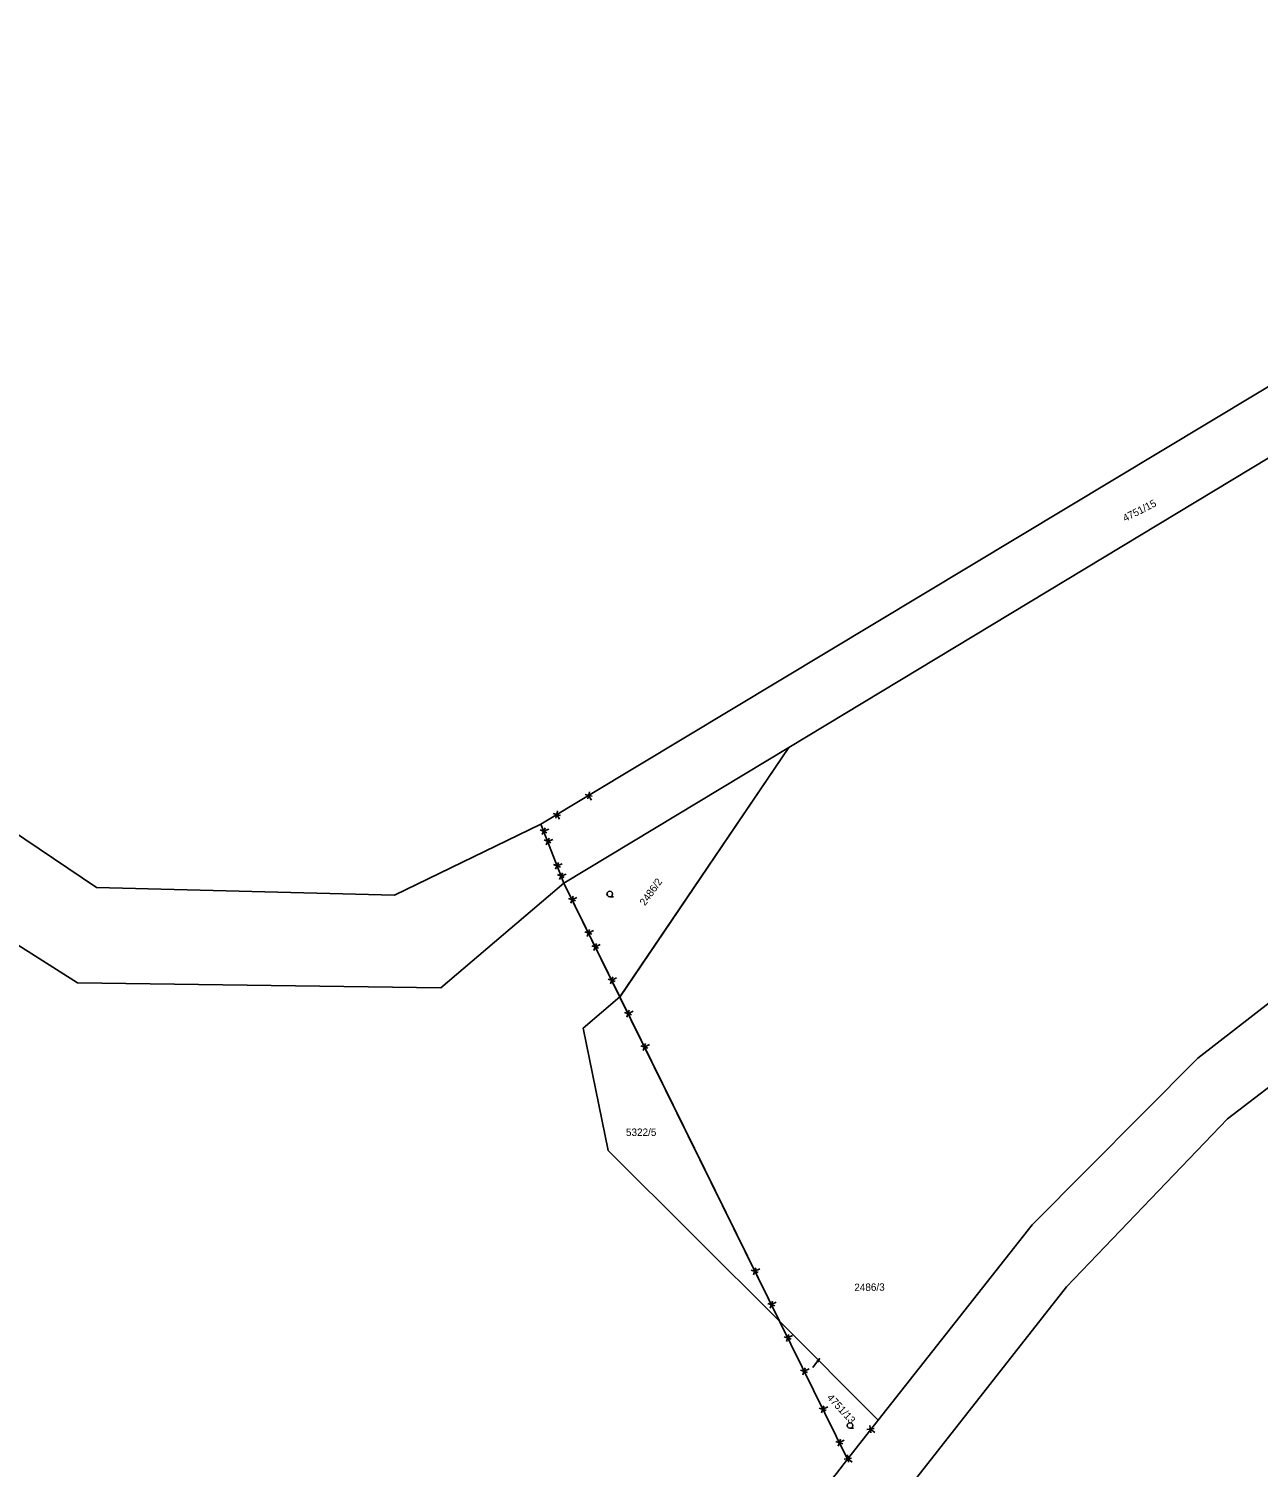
# Model space of a CAD drawing. Extents: x -439750 to -439180, y -1258684 to -1258308.
# Drawn here: x -439610.6 to -439544.4, y -1258440.1 to -1258362.6 of the extents above; entities that cross this region are included whole.
import ezdxf

# ---------------------------------------------------------------- set-up
doc = ezdxf.new("R2010")
doc.units = 0
doc.layers.add('KATASTER', color=7, linetype='Continuous')
doc.layers.add('UOV', color=7, linetype='Continuous')

# ---------------------------------------------------------------- blocks, each defined once
blk = doc.blocks.new('SIPKA_2')
blk.add_line((-0.2, 2), (0, 3))
blk.add_lwpolyline([(0, 0), (0, 3), (0.2, 2)])
blk = doc.blocks.new('304')
blk.add_lwpolyline([(0, 0), (-0.38, 0.1), (-0.65, 0.37), (-0.75, 0.74), (-0.65, 1.11), (-0.38, 1.38), (-0.01, 1.48), (0.36, 1.38), (0.63, 1.11), (0.73, 0.73), (0.63, 0.35), (0.36, 0.08), (-0.02, -0.02), (0.98, -0.02)])
blk = doc.blocks.new('2072')
for p, q in [((-4.3, 0.7), (-5.7, -0.7)), ((-5.7, 0.7), (-4.3, -0.7)), ((-5, 0), (-5, -1.5)), ((4.3, 0.7), (5.7, -0.7)), ((5.7, 0.7), (4.3, -0.7)), ((5, 0), (5, -1.5))]:
    blk.add_line(p, q)

msp = doc.modelspace()

# ---------------------------------------------------------------- linework, layer by layer
at = {"layer": 'KATASTER'}
for points in [[(-439562.436, -1258308.807), (-439517.56, -1258326.72), (-439510.66, -1258363.93), (-439529.05, -1258372.98), (-439583.01, -1258405.44), (-439590.88, -1258409.26), (-439606.92, -1258408.85), (-439661.16, -1258372.28), (-439678.1, -1258360.24), (-439700.63, -1258331.393)], [(-439700.63, -1258331.393), (-439678.1, -1258360.24), (-439661.16, -1258372.28), (-439606.92, -1258408.85), (-439590.88, -1258409.26), (-439583.01, -1258405.44), (-439581.78, -1258408.62), (-439588.39, -1258414.26), (-439607.94, -1258413.98), (-439664.32, -1258378.2), (-439680.32, -1258364.89), (-439706.952, -1258332.427)], [(-439680.32, -1258364.89), (-439664.32, -1258378.2), (-439607.94, -1258413.98), (-439588.39, -1258414.26), (-439581.78, -1258408.62), (-439578.76, -1258414.75), (-439570.17, -1258432.21), (-439566.51, -1258439.64), (-439567.09, -1258440.4), (-439572.34, -1258446.7), (-439579.1, -1258452.12), (-439586.76, -1258455.52), (-439594.1, -1258457.31), (-439604.91, -1258457.14), (-439610.82, -1258457.46), (-439627.78, -1258463.49), (-439614.4, -1258450.89), (-439625.47, -1258430.92), (-439655.75, -1258405.12), (-439680.64, -1258393.46)], [(-439529.05, -1258372.98), (-439583.01, -1258405.44), (-439581.78, -1258408.62), (-439578.76, -1258414.75), (-439570.17, -1258432.21), (-439566.51, -1258439.64), (-439567.09, -1258440.4), (-439572.34, -1258446.7), (-439579.1, -1258452.12), (-439586.76, -1258455.52), (-439594.1, -1258457.31), (-439604.91, -1258457.14), (-439610.82, -1258457.46), (-439627.78, -1258463.49), (-439614.4, -1258450.89), (-439625.47, -1258430.92), (-439655.75, -1258405.12), (-439680.64, -1258393.46)], [(-439680.64, -1258393.46), (-439655.75, -1258405.12), (-439625.47, -1258430.92), (-439614.4, -1258450.89), (-439627.78, -1258463.49), (-439610.82, -1258457.46), (-439604.91, -1258457.14), (-439594.1, -1258457.31), (-439586.76, -1258455.52), (-439579.1, -1258452.12), (-439572.34, -1258446.7), (-439567.09, -1258440.4), (-439566.51, -1258439.64), (-439570.17, -1258432.21), (-439578.76, -1258414.75), (-439581.78, -1258408.62), (-439583.01, -1258405.44), (-439529.05, -1258372.98)], [(-439527.84, -1258376.06), (-439569.67, -1258401.31), (-439581.78, -1258408.62), (-439583.01, -1258405.44), (-439529.05, -1258372.98)], [(-439537.73, -1258410.35), (-439547.65, -1258418.05), (-439556.57, -1258427.01), (-439564.85, -1258437.53), (-439570.17, -1258432.21), (-439578.76, -1258414.75), (-439569.67, -1258401.31), (-439527.84, -1258376.06)], [(-439660.49, -1258516.44), (-439665.91, -1258502.4), (-439666.82, -1258496.88), (-439665.48, -1258490.84), (-439662.74, -1258486.44), (-439657.56, -1258481.06), (-439653.51, -1258478.38), (-439649.29, -1258475.58), (-439627.78, -1258463.49), (-439610.82, -1258457.46), (-439604.91, -1258457.14), (-439594.1, -1258457.31), (-439586.76, -1258455.52), (-439579.1, -1258452.12), (-439572.34, -1258446.7), (-439567.09, -1258440.4), (-439566.51, -1258439.64), (-439564.85, -1258437.53), (-439556.57, -1258427.01), (-439547.65, -1258418.05), (-439537.73, -1258410.35)], [(-439536.05, -1258413.64), (-439546.05, -1258421.31), (-439554.71, -1258430.36), (-439570.11, -1258449.98), (-439574.47, -1258453.63), (-439580.2, -1258456.85), (-439586.86, -1258459.56), (-439593.42, -1258460.84), (-439598.86, -1258460.62), (-439604.63, -1258460.39), (-439610.67, -1258460.8), (-439615.1, -1258461.87), (-439623.26, -1258465.49), (-439629.03, -1258468.61), (-439635.72, -1258471.93), (-439658.88, -1258489.54), (-439659.88, -1258488.91), (-439662.11, -1258495.3), (-439662.28, -1258501.2), (-439658.45, -1258512.88)], [(-439541.07, -1258454.21), (-439546.64, -1258459.47), (-439551.33, -1258468.47), (-439560.37, -1258460.62), (-439570.11, -1258449.98), (-439554.71, -1258430.36), (-439546.05, -1258421.31), (-439536.05, -1258413.64)]]:
    msp.add_lwpolyline(points, dxfattribs=at)
for points in [[(-439578.76, -1258414.75), (-439581.78, -1258408.62), (-439569.67, -1258401.31)], [(-439564.85, -1258437.53), (-439566.51, -1258439.64), (-439570.17, -1258432.21)]]:
    msp.add_lwpolyline(points, close=True, dxfattribs=at)
at = {"layer": 'UOV'}
for points in [[(-439700.63, -1258331.393), (-439678.1, -1258360.24), (-439661.16, -1258372.28), (-439606.92, -1258408.85), (-439590.88, -1258409.26), (-439583.01, -1258405.44), (-439581.78, -1258408.62), (-439588.39, -1258414.26), (-439607.94, -1258413.98), (-439661.77, -1258379.82), (-439664.29, -1258372.6), (-439677.47, -1258360.86), (-439697.57, -1258343.86), (-439706.951, -1258332.426)], [(-439529.05, -1258372.98), (-439583.01, -1258405.44), (-439590.88, -1258409.26), (-439606.92, -1258408.85), (-439661.16, -1258372.28), (-439678.1, -1258360.24), (-439700.63, -1258331.393)], [(-439614.4, -1258450.89), (-439625.47, -1258430.92), (-439655.75, -1258405.12), (-439671.11, -1258397.93), (-439675.75, -1258393.93), (-439665.91, -1258391.35), (-439662.68, -1258387.9), (-439661.1, -1258381.73), (-439661.77, -1258379.82), (-439607.94, -1258413.98), (-439588.39, -1258414.26), (-439581.78, -1258408.62), (-439578.76, -1258414.74), (-439580.73, -1258416.42), (-439579.38, -1258423.01), (-439570.17, -1258432.21), (-439566.51, -1258439.64), (-439567.09, -1258440.4)], [(-439567.09, -1258440.4), (-439566.51, -1258439.64), (-439564.85, -1258437.53), (-439556.57, -1258427.01), (-439547.65, -1258418.05), (-439537.73, -1258410.35)], [(-439536.05, -1258413.64), (-439546.05, -1258421.31), (-439554.71, -1258430.36), (-439570.11, -1258449.98)]]:
    msp.add_lwpolyline(points, dxfattribs=at)
for points in [[(-439583.01, -1258405.44), (-439529.05, -1258372.98), (-439510.66, -1258363.93), (-439510.27, -1258366.98), (-439513.27, -1258367.25), (-439515.07, -1258371.54), (-439519.61, -1258372.16), (-439523.86, -1258373.74), (-439527.84, -1258376.06), (-439569.67, -1258401.31), (-439578.76, -1258414.74), (-439581.78, -1258408.62)], [(-439570.17, -1258432.21), (-439579.38, -1258423.01), (-439580.73, -1258416.42), (-439578.76, -1258414.74)], [(-439566.51, -1258439.64), (-439570.17, -1258432.21), (-439564.85, -1258437.53)]]:
    msp.add_lwpolyline(points, close=True, dxfattribs=at)

# ---------------------------------------------------------------- block references
at = {"layer": 'KATASTER'}
for name, p, xscale, yscale, rotation in [('2072', (-439581.296, -1258404.409), 0.2, 0.20000000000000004, 31.054311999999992), ('2072', (-439582.501, -1258406.755), 0.2, 0.19999999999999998, 111.153812), ('2072', (-439582.289, -1258407.305), 0.2, 0.19999999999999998, 111.153812), ('2072', (-439580.896, -1258410.414), 0.2, 0.19999999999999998, 116.25313700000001), ('2072', (-439579.644, -1258412.956), 0.2, 0.19999999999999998, 116.25313700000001), ('2072', (-439577.877, -1258416.545), 0.20000000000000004, 0.2, 116.19584099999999), ('2072', (-439571.053, -1258430.415), 0.20000000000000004, 0.2, 116.19584099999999), ('2072', (-439569.286, -1258434.004), 0.2, 0.19999999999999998, 116.25313700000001), ('SIPKA_2', (-439568.37, -1258434.7), 0.2, 0.19999999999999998, -36.85180400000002), ('2072', (-439567.394, -1258437.846), 0.2, 0.19999999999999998, 116.25313700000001), ('2072', (-439565.877, -1258438.81), 0.2, 0.19999999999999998, 52.654821)]:
    msp.add_blockref(name, p, dxfattribs=dict(at, xscale=xscale, yscale=yscale, rotation=rotation))
at = {"layer": 'KATASTER', "xscale": 0.2, "yscale": 0.20000000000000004}
for p in [(-439579.3, -1258409.35), (-439566.37, -1258437.97)]:
    msp.add_blockref('304', p, dxfattribs=at)

# ---------------------------------------------------------------- texts
at = {"layer": 'KATASTER'}
for s, rotation, p in [('2486/2', 54.259, (-439577.404, -1258409.867)), ('2486/3', 0.688, (-439566.137, -1258430.584))]:
    msp.add_text(s, height=0.4, rotation=rotation, dxfattribs=at).set_placement(p)
at = {"layer": 'UOV'}
for s, rotation, p in [('4751/15', 27.044, (-439551.56, -1258389.175)), ('4751/13', 312.72, (-439567.641, -1258436.343))]:
    msp.add_text(s, height=0.4, rotation=rotation, dxfattribs=at).set_placement(p)
msp.add_text('5322/5', height=0.4, dxfattribs=at).set_placement((-439578.429, -1258422.231))

doc.saveas('drawing.dxf')
